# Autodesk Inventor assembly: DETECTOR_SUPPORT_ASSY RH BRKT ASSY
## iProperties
Shininess: 64.0
Length Units: 11272
Angle Units: 11279
Time Units: 11290
Mass Units: 11286
Length Display Precision: 3
Angle Display Precision: 2
Compacted: True
Part Number: DETECTOR_SUPPORT_ASSY RH BRKT ASSY
Document SubType Name: Assembly
Created: 2004-08
Designer: John Blackburn
Manufacturer: Standard
Standards Organization: Custom
Density: 0.0
Volumn: 0.0
Area: 0.0
PropertySet Name: Model Information
Control State: 0
Master: False
Checked Out: False
Author: John Blackburn
